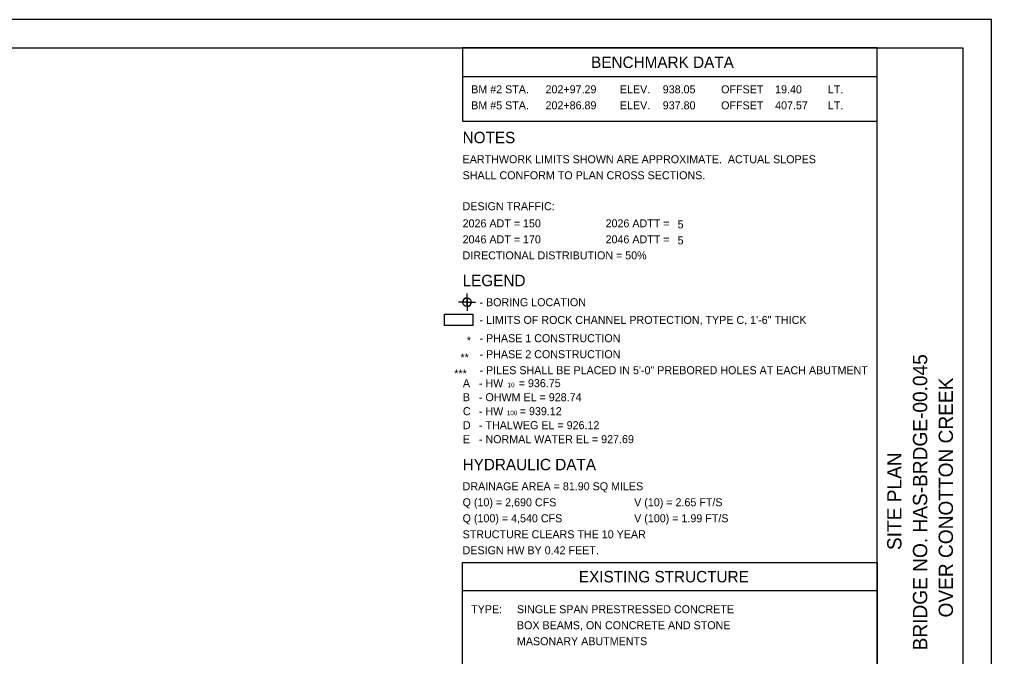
# Model space of a CAD drawing. Extents: x 0 to 34, y 0 to 22.
# Drawn here: x 17 to 34, y 10.85 to 22 of the extents above; entities that cross this region are included whole.
import ezdxf

# ---------------------------------------------------------------- set-up
doc = ezdxf.new("R2010")
doc.units = 0
for name, color, linetype in [('BR_X_Slab_Object', 7, 'Continuous'), ('BR_X_SV_Bottom_of_Beam', 7, 'Continuous'), ('DR_X_Drive_Pipe', 7, 'Continuous'), ('DT_P_Contour_Minor', 7, 'Continuous'), ('GM_X_Rail_Line', 7, 'Continuous')]:
    doc.layers.add(name, color=color, linetype=linetype)

msp = doc.modelspace()

# ---------------------------------------------------------------- linework, layer by layer
at = {"layer": 'BR_X_Slab_Object'}
msp.add_lwpolyline([(0, 0), (34, 0), (34, 22), (0, 22)], close=True, dxfattribs=at)
at = {"layer": 'BR_X_SV_Bottom_of_Beam'}
for p, q in [((24.827, 17.051), (24.827, 17.201)), ((24.827, 17.051), (24.677, 17.051)), ((24.827, 17.051), (24.752, 17.051)), ((24.827, 17.126), (24.827, 17.051)), ((24.827, 17.051), (24.827, 16.901)), ((24.827, 17.051), (24.977, 17.051)), ((24.827, 16.976), (24.827, 17.051)), ((24.827, 17.051), (24.902, 17.051))]:
    msp.add_line(p, q, dxfattribs=at)
msp.add_circle((24.827, 17.051), 0.075, dxfattribs=at)
for start, end in [(90, 180), (270, 360)]:
    msp.add_arc((24.827, 17.051), 0.075, start, end, dxfattribs=at)
at = {"layer": 'DR_X_Drive_Pipe'}
for p, q in [((24.75, 21), (32, 21)), ((32, 11.998), (24.75, 11.998))]:
    msp.add_line(p, q, dxfattribs=at)
for points in [[(32, 21.5), (24.75, 21.5), (24.75, 20.22), (32, 20.22)], [(24.431, 16.841), (24.931, 16.841), (24.931, 16.641), (24.431, 16.641)], [(24.75, 12.498), (32, 12.498), (32, 6.884), (24.75, 6.884)]]:
    msp.add_lwpolyline(points, close=True, dxfattribs=at)
at = {"layer": 'DT_P_Contour_Minor'}
msp.add_lwpolyline([(24.431, 16.841), (24.931, 16.841), (24.931, 16.641), (24.431, 16.641)], close=True, dxfattribs=at)
at = {"layer": 'GM_X_Rail_Line'}
msp.add_line((32, 0.5), (32, 21.5), dxfattribs=at)
msp.add_lwpolyline([(1.5, 21.5), (33.5, 21.5), (33.5, 0.5), (1.5, 0.5)], close=True, dxfattribs=at)

# ---------------------------------------------------------------- texts
at = {"layer": 'DR_X_Drive_Pipe'}
for s, height, p in [('BENCHMARK DATA', 0.2, (26.997, 21.15)), ('BM #2 STA.', 0.14, (24.9, 20.707)), ('202+97.29', 0.14, (26.2, 20.707)), ('ELEV.', 0.14, (27.5, 20.707)), ('938.05', 0.14, (28.25, 20.707)), ('OFFSET', 0.14, (29.271, 20.707)), ('19.40', 0.14, (30.215, 20.707)), ('LT.', 0.14, (31.138, 20.707)), ('BM #5 STA.', 0.14, (24.9, 20.427)), ('202+86.89', 0.14, (26.2, 20.427)), ('ELEV.', 0.14, (27.5, 20.427)), ('937.80', 0.14, (28.25, 20.427)), ('OFFSET', 0.14, (29.271, 20.427)), ('407.57', 0.14, (30.215, 20.427)), ('LT.', 0.14, (31.138, 20.427)), ('NOTES', 0.2, (24.75, 19.833)), ('EARTHWORK LIMITS SHOWN ARE APPROXIMATE.  ACTUAL SLOPES', 0.14, (24.75, 19.483)), ('SHALL CONFORM TO PLAN CROSS SECTIONS.', 0.14, (24.75, 19.203)), ('DESIGN TRAFFIC:', 0.14, (24.75, 18.661)), ('2026 ADT = 150', 0.14, (24.75, 18.361)), ('2026 ADTT =', 0.14, (27.25, 18.361)), ('5', 0.14, (28.509, 18.344)), ('2046 ADT = 170', 0.14, (24.75, 18.081)), ('2046 ADTT =', 0.14, (27.25, 18.081)), ('5', 0.14, (28.509, 18.064)), ('DIRECTIONAL DISTRIBUTION =', 0.14, (24.75, 17.801)), ('50%   ', 0.14, (27.593, 17.801)), ('LEGEND', 0.2, (24.75, 17.331)), ('- BORING LOCATION', 0.14, (25.045, 16.981)), ('- LIMITS OF ROCK CHANNEL PROTECTION, TYPE C, 1\'-6" THICK', 0.14, (25.045, 16.671)), ('- PHASE 1 CONSTRUCTION', 0.14, (25.045, 16.351)), ('- PHASE 2 CONSTRUCTION', 0.14, (25.045, 16.071)), ('- PILES SHALL BE PLACED IN 5\'-0" PREBORED HOLES AT EACH ABUTMENT', 0.14, (25.045, 15.791)), ('HYDRAULIC DATA', 0.2, (24.75, 14.11)), ('DRAINAGE AREA = 81.90 SQ MILES', 0.14, (24.75, 13.76)), ('Q (10) = 2,690 CFS', 0.14, (24.75, 13.48)), ('V (10) = 2.65 FT/S', 0.14, (27.75, 13.48)), ('Q (100) = 4,540 CFS', 0.14, (24.75, 13.2)), ('V (100) = 1.99 FT/S', 0.14, (27.75, 13.2)), ('STRUCTURE CLEARS THE 10 YEAR ', 0.14, (24.75, 12.92)), ('DESIGN HW BY 0.42 FEET.', 0.14, (24.75, 12.64)), ('EXISTING STRUCTURE', 0.2, (26.783, 12.148)), ('TYPE:', 0.14, (24.9, 11.608)), ('SINGLE SPAN PRESTRESSED CONCRETE                  ', 0.14, (25.7, 11.608)), ('BOX BEAMS, ON CONCRETE AND STONE                  ', 0.14, (25.7, 11.328)), ('MASONARY ABUTMENTS                                ', 0.14, (25.7, 11.048))]:
    msp.add_text(s, height=height, dxfattribs=at).set_placement(p)
for s, p in [('BRIDGE NO. HAS-BRDGE-00.045', (32.875, 10.958)), ('OVER CONOTTON CREEK', (33.325, 11.534)), ('SITE PLAN', (32.425, 12.714))]:
    msp.add_text(s, height=0.25, rotation=90, dxfattribs=at).set_placement(p)
at = {"layer": 'DT_P_Contour_Minor'}
for s, height, p in [('*', 0.14, (24.823, 16.312)), ('**', 0.14, (24.713, 16.015)), ('***', 0.14, (24.604, 15.735)), ('A ', 0.14, (24.755, 15.564)), ('- HW ', 0.14, (25.035, 15.564)), ('10', 0.08, (25.536, 15.564)), (' = 936.75', 0.14, (25.679, 15.564)), ('B', 0.14, (24.755, 15.319)), ('- OHWM EL = 928.74', 0.14, (25.035, 15.319)), ('C ', 0.14, (24.755, 15.074)), ('- HW', 0.14, (25.035, 15.074)), ('100', 0.08, (25.522, 15.074)), ('= 939.12', 0.14, (25.749, 15.074)), ('D ', 0.14, (24.755, 14.829)), ('- THALWEG EL = 926.12', 0.14, (25.035, 14.829)), ('E ', 0.14, (24.755, 14.584)), ('- NORMAL WATER EL = 927.69', 0.14, (25.035, 14.584))]:
    msp.add_text(s, height=height, dxfattribs=at).set_placement(p)

doc.saveas('drawing.dxf')
